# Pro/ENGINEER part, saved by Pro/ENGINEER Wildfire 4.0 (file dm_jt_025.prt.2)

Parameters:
  METRIC = "NO"

Other parameters: PITCH, DRILL_POINT_ANGLE, DRILL_DEPTH, DRILL_DIAMETER, THREAD_DIAMETER, THREADS_PER_INCH, THREAD_DEPTH, THREAD_LENGTH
